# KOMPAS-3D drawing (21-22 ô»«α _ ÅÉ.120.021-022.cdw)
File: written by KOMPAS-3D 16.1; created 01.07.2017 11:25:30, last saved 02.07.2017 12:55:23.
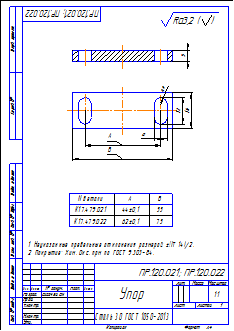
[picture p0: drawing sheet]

Sheet 1: A4, portrait

Title block, sheet 1: name: Упор; designation: ПР.120.021; ПР.120.022; material: Сталь 30 ГОСТ 1050-2013; scale: 1:1; sheets: 1; sheet format: A4; stored path: D:\VSE\Эрга\Оснастка\Гибка лепестков\Прохвост\Скоба _ К17.479.019.cdw; drawn by: Сигачев СИ

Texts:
  Sergey
  N детали
  Неуказанные предельные отклонения размеров  (IT 14)/2.
  Покрытие: Хим. Окс. прм по ГОСТ 9.303-84.
  Ra3,2
  Ra3,2 ( )
Dimensions and other numbers on the sheet: 44 0,1; 55; 62 0,1; 75; 5; 3; 6; 12; 16; 1:1; 1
